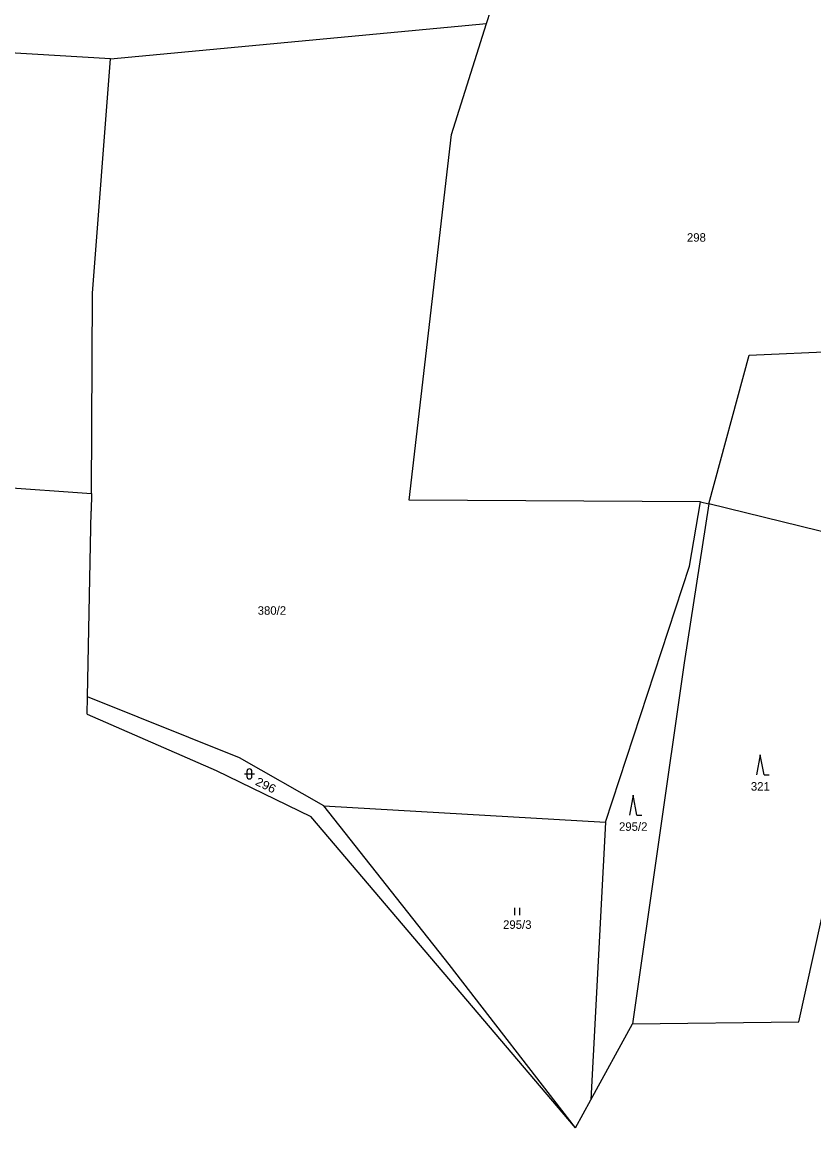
# Model space of a CAD drawing. Extents: x -791548 to -789311, y -1142631 to -1140855.
# Drawn here: x -791288.6 to -791130.2, y -1141919.4 to -1141698.3 of the extents above; entities that cross this region are included whole.
import ezdxf
from ezdxf.enums import TextEntityAlignment as Align

# ---------------------------------------------------------------- set-up
doc = ezdxf.new("R2010")
doc.units = 0
doc.header["$LTSCALE"] = 0.68
doc.layers.add('1', color=7, linetype='Continuous', lineweight=25)
doc.layers.add('3', color=7, linetype='Continuous', lineweight=25)
doc.layers.add('2', color=7, linetype='Continuous')

msp = doc.modelspace()

# ---------------------------------------------------------------- linework, layer by layer
at = {"layer": '1'}
for p, q in [((-791195.71, -1141698.56), (-791194.85, -1141695.89)), ((-791270.89, -1141705.66), (-791195.71, -1141698.56)), ((-791202.68, -1141720.75), (-791195.71, -1141698.56)), ((-791211.14, -1141793.88), (-791202.68, -1141720.75)), ((-791274.7, -1141792.53), (-791274.49, -1141752.52)), ((-791143.13, -1141764.92), (-791107.74, -1141763.23)), ((-791151.22, -1141794.61), (-791143.13, -1141764.92)), ((-791312.52, -1141789.87), (-791274.7, -1141792.53)), ((-791274.7, -1141792.53), (-791274.78, -1141796.11)), ((-791152.91, -1141794.24), (-791211.14, -1141793.88)), ((-791155.11, -1141807.06), (-791152.91, -1141794.24)), ((-791152.91, -1141794.24), (-791151.22, -1141794.61)), ((-791275.53, -1141833.21), (-791274.78, -1141796.11)), ((-791171.9, -1141858.28), (-791155.11, -1141807.06)), ((-791156.16, -1141826.4), (-791166.46, -1141898.6)), ((-791275.6, -1141836.68), (-791275.53, -1141833.21)), ((-791245.1, -1141845.43), (-791275.53, -1141833.21)), ((-791275.6, -1141836.68), (-791249.74, -1141847.93)), ((-791228.22, -1141854.97), (-791245.1, -1141845.43)), ((-791249.74, -1141847.93), (-791230.85, -1141857.16)), ((-791203.16, -1141886.72), (-791228.22, -1141854.97)), ((-791177.87, -1141919.39), (-791230.85, -1141857.16)), ((-791133.22, -1141898.19), (-791125.69, -1141864.1)), ((-791177.87, -1141919.39), (-791203.16, -1141886.72)), ((-791166.46, -1141898.6), (-791133.22, -1141898.19)), ((-791174.8, -1141913.79), (-791166.46, -1141898.6)), ((-791177.87, -1141919.39), (-791174.8, -1141913.79))]:
    msp.add_line(p, q, dxfattribs=at)
for points in [[(-791274.49, -1141752.52), (-791270.89, -1141705.66), (-791292.15, -1141704.35)], [(-791110.72, -1141804.53), (-791151.22, -1141794.61), (-791156.16, -1141826.4)], [(-791228.22, -1141854.97), (-791171.9, -1141858.28), (-791174.8, -1141913.79)]]:
    msp.add_lwpolyline(points, dxfattribs=at)
at = {"layer": '3'}
for p, q in [((-791244.121, -1141848.611), (-791242.119, -1141848.611)), ((-791243.621, -1141848.111), (-791243.621, -1141849.112)), ((-791242.619, -1141849.112), (-791242.619, -1141848.111)), ((-791140.16, -1141848.83), (-791139.164, -1141848.83)), ((-791165.59, -1141856.86), (-791164.594, -1141856.86)), ((-791190.041, -1141876.87), (-791190.041, -1141875.37)), ((-791189.04, -1141876.87), (-791189.04, -1141875.37))]:
    msp.add_line(p, q, dxfattribs=at)
for points in [[(-791140.16, -1141848.83), (-791140.91, -1141844.83), (-791141.66, -1141848.83)], [(-791165.59, -1141856.86), (-791166.34, -1141852.86), (-791167.09, -1141856.86)]]:
    msp.add_lwpolyline(points, dxfattribs=at)
for centre, start, end in [((-791243.12, -1141848.1109), 0, 180), ((-791243.12, -1141849.1109), 180, 359.98789)]:
    msp.add_arc(centre, 0.5, start, end, dxfattribs=at)

# ---------------------------------------------------------------- texts
at = {"layer": '2'}
for s, p in [('298', (-791153.699, -1141742.202)), ('380/2', (-791238.62, -1141816.792)), ('321', (-791140.909, -1141851.962)), ('295/2', (-791166.34, -1141859.992)), ('295/3', (-791189.53, -1141879.592))]:
    msp.add_text(s, height=1.7, dxfattribs=at).set_placement(p, align=Align.CENTER)
at = {"layer": '2', "width": 1.1}
msp.add_text('296', height=1.7, rotation=334, dxfattribs=at).set_placement((-791240.2116, -1141851.6355), align=Align.CENTER)

doc.saveas('drawing.dxf')
